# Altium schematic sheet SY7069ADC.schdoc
size 127 x 101 mm
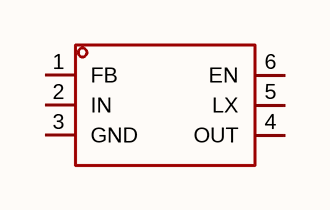
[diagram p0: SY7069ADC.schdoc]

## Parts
U?  sy7069adc  [SOT-23-6_L2.9-W1.6-P0.95-LS2.8-BR]  (value not drawn)

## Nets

Not connected (* = marked no-connect by the designer): U? 1(FB) 2(IN) 3(GND) 4(OUT) 5(LX) 6(EN)

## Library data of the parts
U? = sy7069adc: 功能类型:升压型;工作电压:2.5V~5.5V;输出电压:2.5V~5.5V;输出电流:3A;输出类型:可调;; Manufacturer: Silergy(矽力杰); AddInBom: yes; ModelId: 18da8f6c14a34920b3e136b5c401a119; ModelName: SOT-23-6_L2.9-W1.6-H1.5-LS2.8-P0.95; ModelTransform: 110.73671,114.173,0,180,0,0,0.001,-0.003,0; Function: 升压型; Output Current: 3A; Frequency - Switching: 1MHz; Synchronous Rectifier: 是; Number of Outputs: 1; Topology: 升压式; Quiescent Current: 32uA; Switch tube (built-in/external): 内置; Output Type: 可调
